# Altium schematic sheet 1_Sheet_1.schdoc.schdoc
size 495 x 241 mm; Name: A_A4; Symbol: A_A4; Device: A_A4; @Project Name: pupnik_2023-12-26_01-16-22; REV: 1.0; Date: 2023-12-25; Sheet: 1/1; Draw By: Penguin Kothe; Company: Your Company; Convert to PCB: yes; Add into BOM: yes
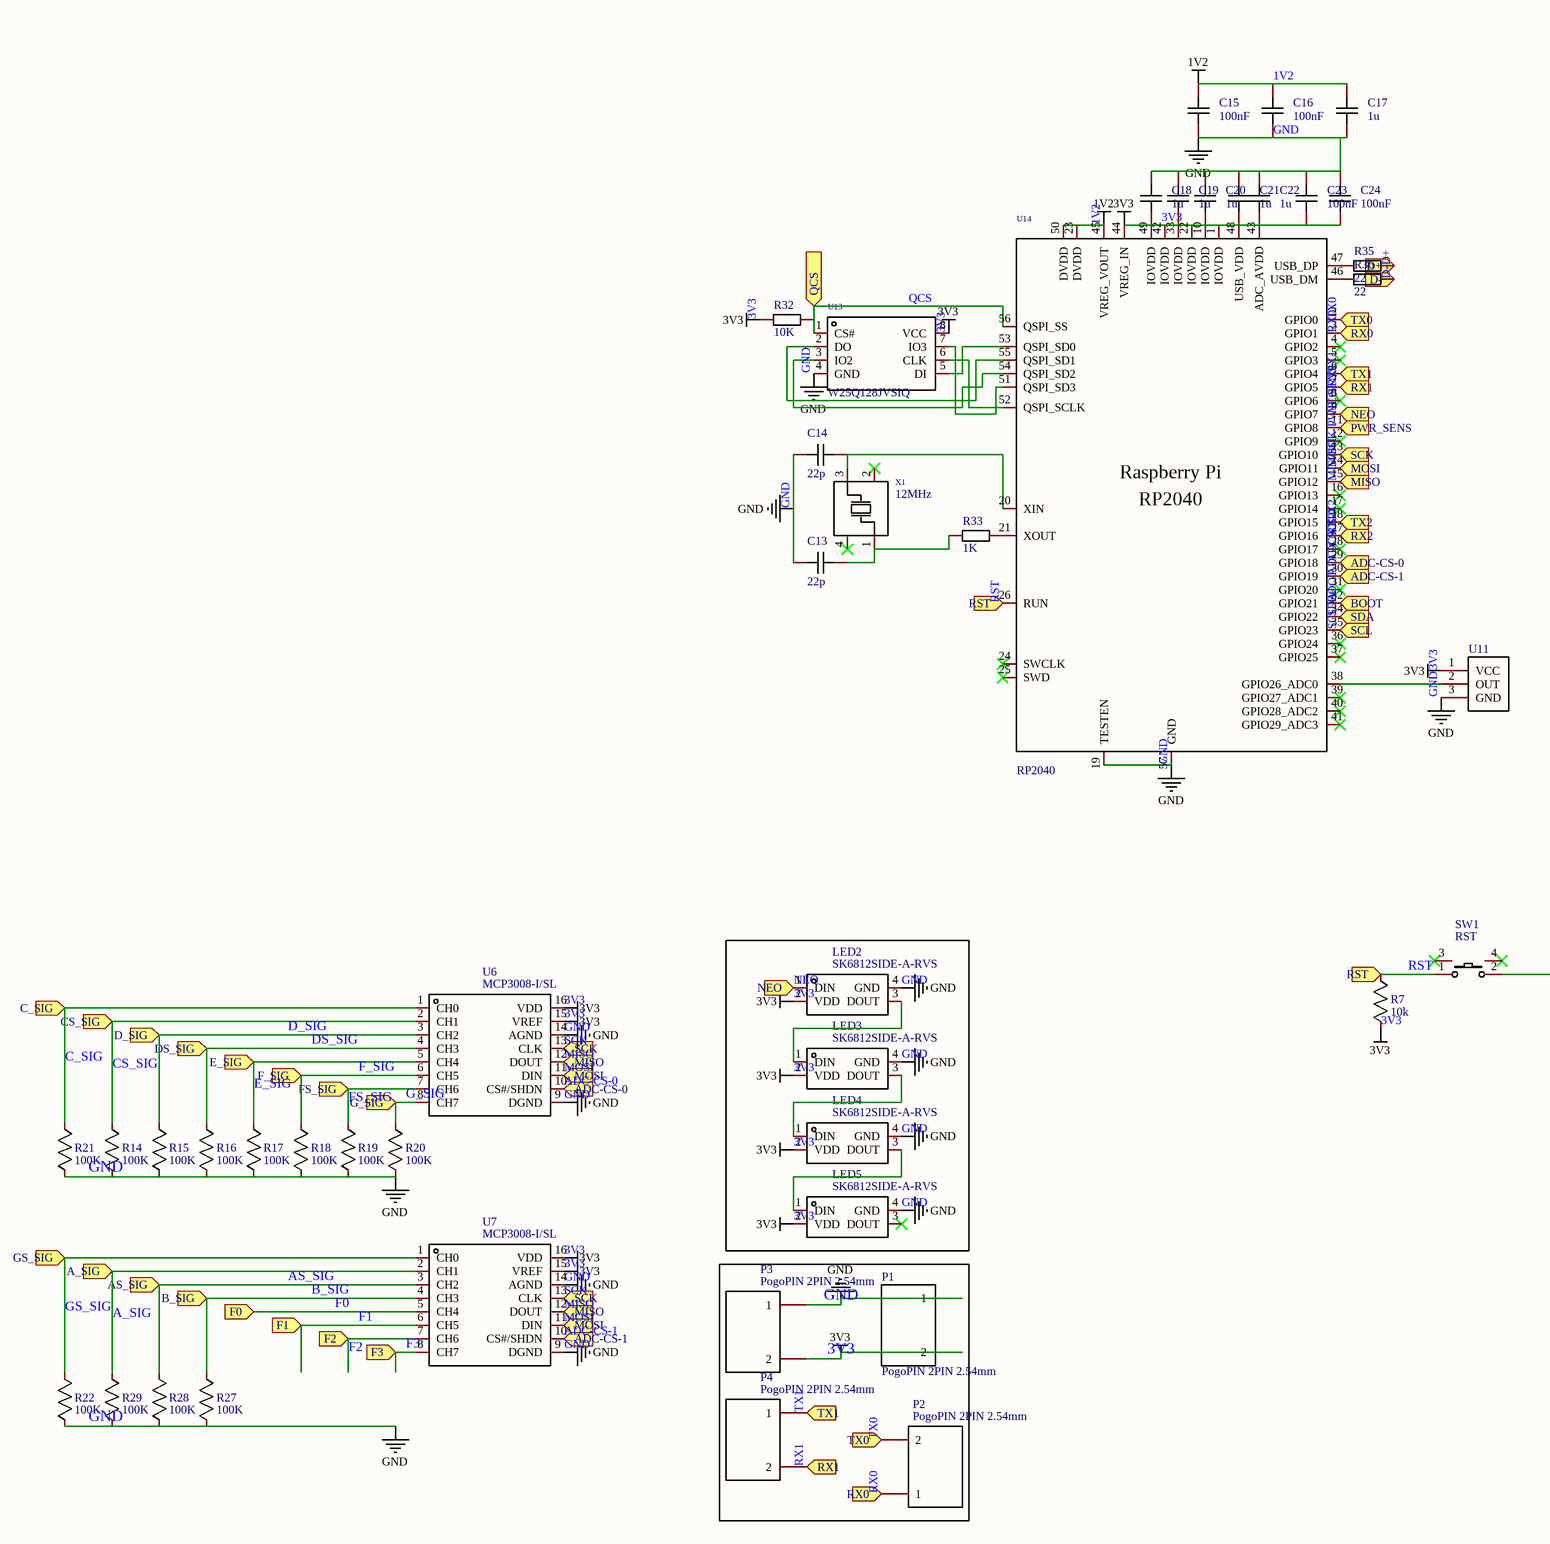
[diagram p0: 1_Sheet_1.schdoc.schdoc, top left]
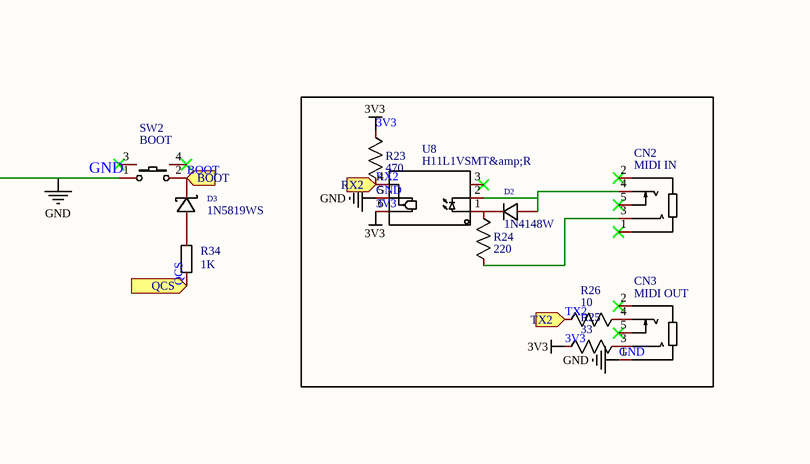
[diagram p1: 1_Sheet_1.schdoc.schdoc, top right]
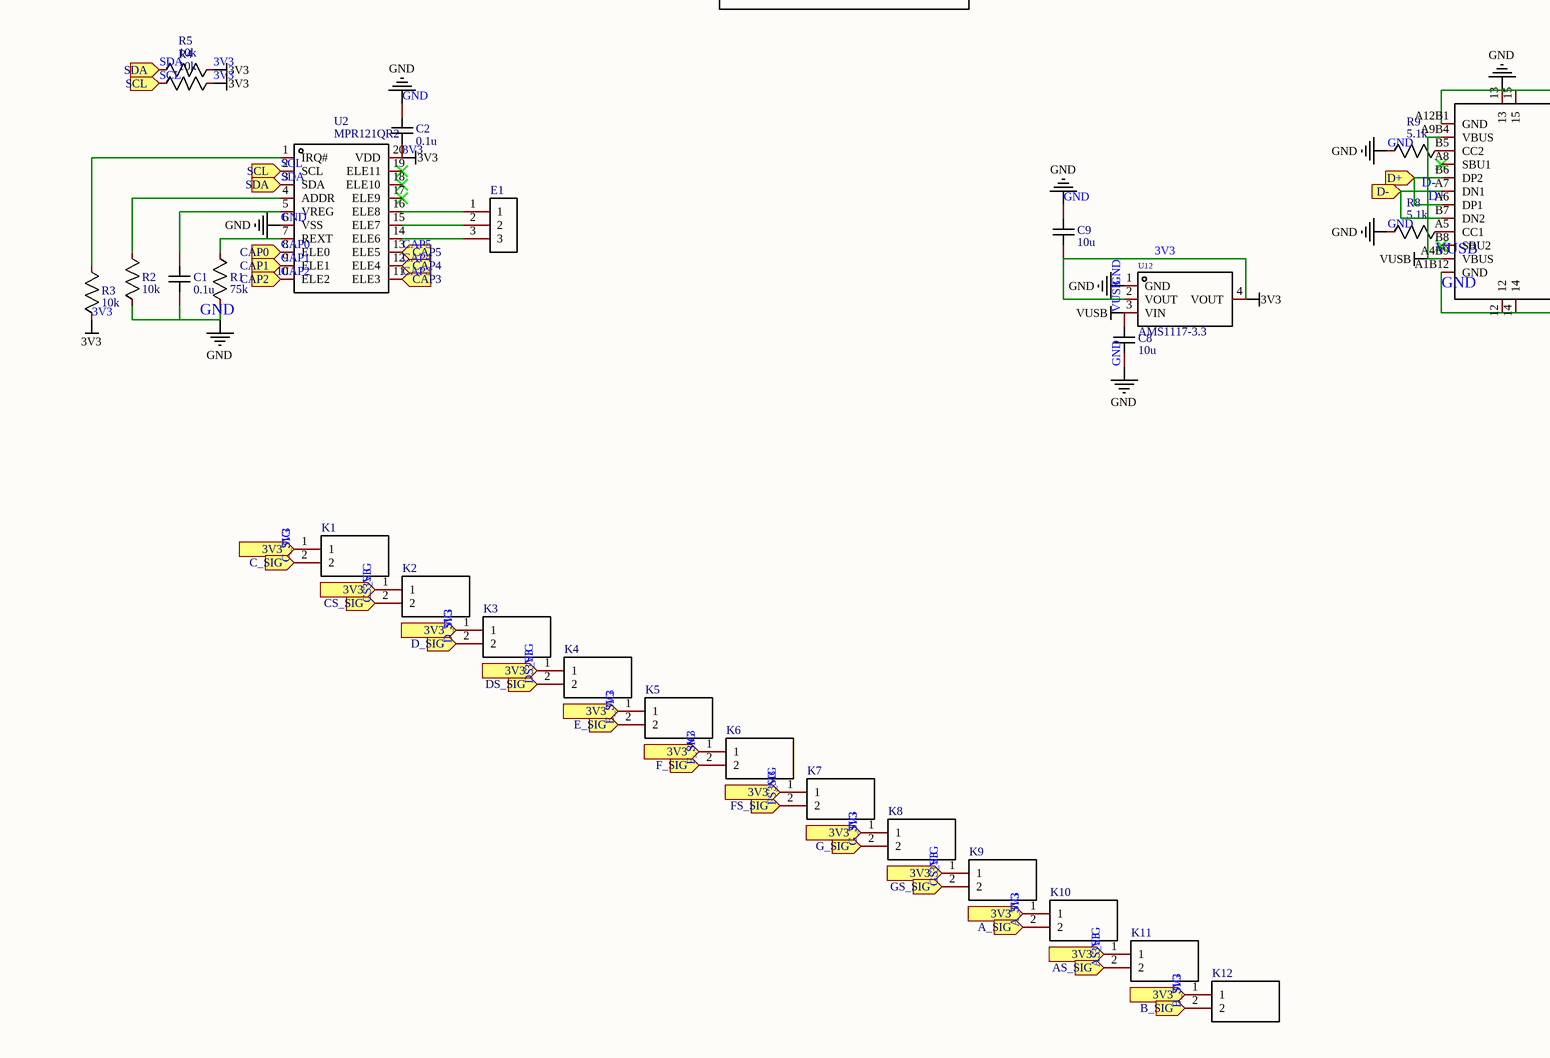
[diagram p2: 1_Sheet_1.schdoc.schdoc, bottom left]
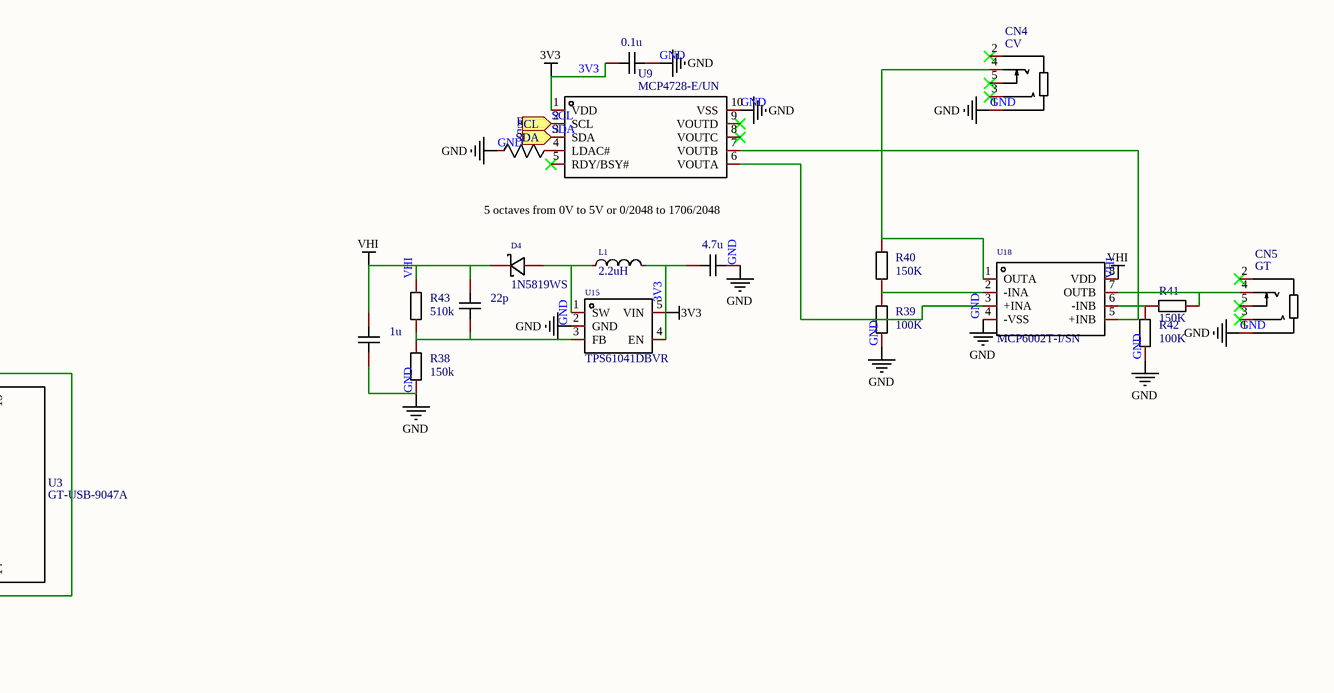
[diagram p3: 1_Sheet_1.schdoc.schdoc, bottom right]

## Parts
C1  0.1u  [C0603]
C2  0.1u  [C0603]
C8  10u  [C0603]
C9  10u  [C0603]
C12  0.1u  [C0603]
C13  22p  [C0603]
C14  22p  [C0603]
C15  100nF  [C0603]
C16  100nF  [C0603]
C17  1u  [C0603]
C18  1u  [C0603]
C19  1u  [C0603]
C20  1u  [C0603]
C21  1u  [C0603]
C22  1u  [C0603]
C23  100nF  [C0603]
C24  100nF  [C0603]
C25  4.7u  [C0603]
C26  22p  [C0603]
C27  1u  [C0603]
CN2  MIDI IN  [AUDIO-SMD_PJ-327A5JJ]
CN3  MIDI OUT  [AUDIO-SMD_PJ-327A5JJ]
CN4  CV  [AUDIO-SMD_PJ-327A5JJ]
CN5  GT  [AUDIO-SMD_PJ-327A5JJ]
D2  1N4148W  [SOD-123F_L2.7-W1.6-LS3.8-RD]
D3  1N5819WS  [SOD-323_L1.8-W1.3-LS2.5-RD]
D4  1N5819WS  [SOD-323_L1.8-W1.3-LS2.5-RD]
E1  enc  [enc]  (value not drawn)
K1  key  [key]  (value not drawn)
K2  key  [key]  (value not drawn)
K3  key  [key]  (value not drawn)
K4  key  [key]  (value not drawn)
K5  key  [key]  (value not drawn)
K6  key  [key]  (value not drawn)
K7  key  [key]  (value not drawn)
K8  key  [key]  (value not drawn)
K9  key  [key]  (value not drawn)
K10  key  [key]  (value not drawn)
K11  key  [key]  (value not drawn)
K12  key  [key]  (value not drawn)
L1  2.2uH  [L0805]
LED2  SK6812SIDE-A-RVS  [LED-SMD_4P-L4.0-W1.6-L]
LED3  SK6812SIDE-A-RVS  [LED-SMD_4P-L4.0-W1.6-L]
LED4  SK6812SIDE-A-RVS  [LED-SMD_4P-L4.0-W1.6-L]
LED5  SK6812SIDE-A-RVS  [LED-SMD_4P-L4.0-W1.6-L]
P1  PogoPIN 2PIN 2.54mm  [POGOPIN 2PIN 2.5MM]
P2  PogoPIN 2PIN 2.54mm  [POGOPIN 2PIN 2.5MM]
P3  PogoPIN 2PIN 2.54mm  [POGOPIN 2PIN 2.5MM]
P4  PogoPIN 2PIN 2.54mm  [POGOPIN 2PIN 2.5MM]
R1  75k  [R0603]
R2  10k  [R0603]
R3  10k  [R0603]
R4  10k  [R0603]
R5  10k  [R0603]
R7  10k  [R0603]
R8  5.1k  [R0603]
R9  5.1k  [R0603]
R14  100K  [R0603]
R15  100K  [R0603]
R16  100K  [R0603]
R17  100K  [R0603]
R18  100K  [R0603]
R19  100K  [R0603]
R20  100K  [R0603]
R21  100K  [R0603]
R22  100K  [R0603]
R23  470  [R0603]
R24  220  [R0603]
R25  33  [R0603]
R26  10  [R0603]
R27  100K  [R0603]
R28  100K  [R0603]
R29  100K  [R0603]
R30  5.1k  [R0603]
R32  10K  [R0603]
R33  1K  [R0603]
R34  1K  [R0603]
R35  22  [R0402]
R36  22  [R0402]
R38  150k  [R0402]
R39  100K  [R0402]
R40  150K  [R0402]
R41  150K  [R0402]
R42  100K  [R0402]
R43  510k  [R0402]
SW1  RST  [SW-SMD_L4.7-W3.5-P3.35-EH]
SW2  BOOT  [SW-SMD_L4.7-W3.5-P3.35-EH]
U2  MPR121QR2  [QFN-20_L3.0-W3.0-P0.40-BL]
U3  GT-USB-9047A  [USB-C-SMD_GT-USB-9047A]
U6  MCP3008-I/SL  [SOIC-16_L9.9-W3.9-P1.27-LS6.0-BL]
U7  MCP3008-I/SL  [SOIC-16_L9.9-W3.9-P1.27-LS6.0-BL]
U8  H11L1VSMT&amp;R  [SMD-6_L8.6-W6.4-P2.54-LS9.4-BL]
U9  MCP4728-E/UN  [MSOP-10_L3.0-W3.0-P0.50-LS5.0-TL]
U11  farts  [farts]  (value not drawn)
U12  AMS1117-3.3  [SOT-223-3_L6.5-W3.4-P2.30-LS7.0-BR]
U13  W25Q128JVSIQ  [SOIC-8_L5.3-W5.3-P1.27-LS8.0-BL]
U14  RP2040  [LQFN-56_L7.0-W7.0-P0.4-EP]
U15  TPS61041DBVR  [SOT-23-5_L3.0-W1.7-P0.95-LS2.8-BR]
U18  MCP6002T-I/SN  [SOIC-8_L4.9-W3.9-P1.27-LS6.0-BL]
X1  12MHz  [OSC-SMD_4P-L3.2-W2.5-BL]

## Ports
3V3 (in), A_SIG (in), ADC-CS-0 (in), ADC-CS-1 (in), AS_SIG (in), B_SIG (in), BOOT (in), C_SIG (in), CAP0 (in), CAP1 (in), CAP2 (in), CAP3 (in), CAP4 (in), CAP5 (in), CS_SIG (in), D+ (in), D- (in), D_SIG (in), DS_SIG (in), E_SIG (in), F0 (in), F1 (in), F2 (in), F3 (in), F_SIG (in), FS_SIG (in), G_SIG (in), GS_SIG (in), MISO (in), MOSI (in), NEO (in), PWR_SENS (in), QCS (in), RST (in), RX0 (in), RX1 (in), RX2 (in), SCK (in), SCL (in), SDA (in), TX0 (in), TX1 (in), TX2 (in)

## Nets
1V2: C15.1 C16.1 C17.1 U14.23(DVDD) U14.45(VREG_VOUT) U14.50(DVDD)
3V3: C2.1 C9.1 C12.2 C18.2 C19.2 C20.2 C21.2 C22.2 C23.2 C24.2 C25.2 K1.1 K2.1 K3.1 K4.1 K5.1 K6.1 K7.1 K8.1 K9.1 K10.1 K11.1 K12.1 L1.2 LED2.2(VDD) LED3.2(VDD) LED4.2(VDD) LED5.2(VDD) P1.2 P3.2 R3.1 R4.1 R5.1 R7.1 R23.2 R25.2 R32.1 U2.20(VDD) U6.15(VREF) U6.16(VDD) U7.15(VREF) U7.16(VDD) U8.6(VCC) U9.1(VDD) U11.1(VCC) U12.2(VOUT) U12.4(VOUT) U13.8(VCC) U14.1(IOVDD) U14.10(IOVDD) U14.22(IOVDD) U14.33(IOVDD) U14.42(IOVDD) U14.43(ADC_AVDD) U14.44(VREG_IN) U14.48(USB_VDD) U14.49(IOVDD) U15.4(EN) U15.5(VIN) ; port 3V3
D+: C8.2 R35.2 U3.A4B9(VBUS) U3.A6(DP1) U3.A9B4(VBUS) U3.B6(DP2) U12.3(VIN) ; port D+  [also labelled VUSB]
GND: C1.1 C2.2 C8.1 C9.2 C12.1 C13.1 C14.2 C15.2 C16.2 C17.2 C18.1 C19.1 C20.1 C21.1 C22.1 C23.1 C24.1 C25.1 C27.2 CN3.1 CN4.1 CN5.1 LED2.4(GND) LED3.4(GND) LED4.4(GND) LED5.4(GND) P1.1 P3.1 R1.1 R2.1 R8.1 R9.1 R14.1 R15.1 R16.1 R17.1 R18.1 R19.1 R20.1 R21.1 R22.1 R27.1 R28.1 R29.1 R30.1 R38.1 R39.1 R42.1 SW1.2 SW2.1 U2.6(VSS) U3.12 U3.13 U3.14 U3.15 U3.A1B12(GND) U3.A12B1(GND) U6.9(DGND) U6.14(AGND) U7.9(DGND) U7.14(AGND) U8.5(GND) U9.10(VSS) U11.3(GND) U12.1(GND) U13.4(GND) U14.19(TESTEN) U14.57(GND) U15.2(GND) U18.4(-VSS)
VHI: C26.1 C27.1 D4.1(K) R43.2 U18.8(VDD)
A_SIG: K10.2 R29.2 U7.2(CH1) ; port A_SIG
ADC-CS-0: U6.10(CS#/SHDN) U14.29(GPIO18) ; port ADC-CS-0
ADC-CS-1: U7.10(CS#/SHDN) U14.30(GPIO19) ; port ADC-CS-1
AS_SIG: K11.2 R28.2 U7.3(CH2) ; port AS_SIG
B_SIG: K12.2 R27.2 U7.4(CH3) ; port B_SIG
BOOT: D3.1(K) SW2.2 U14.32(GPIO21) ; port BOOT
C_SIG: K1.2 R21.2 U6.1(CH0) ; port C_SIG
CAP0: U2.8(ELE0) ; port CAP0
CAP1: U2.9(ELE1) ; port CAP1
CAP2: U2.10(ELE2) ; port CAP2
CAP3: U2.11(ELE3) ; port CAP3
CAP4: U2.12(ELE4) ; port CAP4
CAP5: U2.13(ELE5) ; port CAP5
CS_SIG: K2.2 R14.2 U6.2(CH1) ; port CS_SIG
D-: R36.2 U3.A7(DN1) U3.B7(DN2) ; port D-
D_SIG: K3.2 R15.2 U6.3(CH2) ; port D_SIG
DS_SIG: K4.2 R16.2 U6.4(CH3) ; port DS_SIG
E_SIG: K5.2 R17.2 U6.5(CH4) ; port E_SIG
F0: U7.5(CH4) ; port F0
F1: U7.6(CH5) ; port F1
F2: U7.7(CH6) ; port F2
F3: U7.8(CH7) ; port F3
F_SIG: K6.2 R18.2 U6.6(CH5) ; port F_SIG
FS_SIG: K7.2 R19.2 U6.7(CH6) ; port FS_SIG
G_SIG: K8.2 R20.2 U6.8(CH7) ; port G_SIG
GS_SIG: K9.2 R22.2 U7.1(CH0) ; port GS_SIG
MISO: U6.12(DOUT) U7.12(DOUT) U14.15(GPIO12) ; port MISO
MOSI: U6.11(DIN) U7.11(DIN) U14.14(GPIO11) ; port MOSI
NEO: LED2.1(DIN) U14.9(GPIO7) ; port NEO
PWR_SENS: U14.11(GPIO8) ; port PWR_SENS
QCS: R32.2 R34.1 U13.1(CS#) U14.56(QSPI_SS) ; port QCS
RST: R7.2 SW1.1 U14.26(RUN) ; port RST
RX0: P2.1 U14.3(GPIO1) ; port RX0
RX1: P4.2 U14.7(GPIO5) ; port RX1
RX2: R23.1 U8.4(VO) U14.27(GPIO16) ; port RX2
SCK: U6.13(CLK) U7.13(CLK) U14.13(GPIO10) ; port SCK
SCL: R4.2 U2.2(SCL) U9.2(SCL) U14.35(GPIO23) ; port SCL
SDA: R5.2 U2.3(SDA) U9.3(SDA) U14.34(GPIO22) ; port SDA
TX0: P2.2 U14.2(GPIO0) ; port TX0
TX1: P4.1 U14.6(GPIO4) ; port TX1
TX2: R26.2 U14.18(GPIO15) ; port TX2
NetC1_2: C1.2 U2.5(VREG)
NetC13_2: C13.2 R33.1 X1.1(OSC1)
NetC14_1: C14.1 U14.20(XIN) X1.3(OSC2)
NetC26_2: C26.2 R38.2 R43.1 U15.3(FB)
NetCN2_3: CN2.3 R24.1
NetCN2_4: CN2.4 D2.2(A) U8.2(C)
NetCN3_3: CN3.3 R25.1
NetCN3_4: CN3.4 R26.1
NetCN4_4: CN4.4 R40.2 U18.1(OUTA)
NetCN5_4: CN5.4 R41.1 U18.7(OUTB)
NetD2_1: D2.1(K) R24.2 U8.1(A)
NetD3_2: D3.2(A) R34.2
NetD4_2: D4.2(A) L1.1 U15.1(SW)
NetE1_1: E1.1 U2.16(ELE8)
NetE1_2: E1.2 U2.15(ELE7)
NetE1_3: E1.3 U2.14(ELE6)
NetLED2_3: LED2.3(DOUT) LED3.1(DIN)
NetLED3_3: LED3.3(DOUT) LED4.1(DIN)
NetLED4_3: LED4.3(DOUT) LED5.1(DIN)
NetR1_2: R1.2 U2.7(REXT)
NetR2_2: R2.2 U2.4(ADDR)
NetR3_2: R3.2 U2.1(IRQ#)
NetR8_2: R8.2 U3.A5(CC1)
NetR9_2: R9.2 U3.B5(CC2)
NetR30_2: R30.2 U9.4(LDAC#)
NetR33_2: R33.2 U14.21(XOUT)
NetR35_1: R35.1 U14.47(USB_DP)
NetR36_1: R36.1 U14.46(USB_DM)
NetR39_2: R39.2 R40.1 U18.2(-INA)
NetR41_2: R41.2 R42.2 U18.6(-INB)
NetU9_6: U9.6(VOUTA) U18.3(+INA)
NetU9_7: U9.7(VOUTB) U18.5(+INB)
NetU11_2: U11.2(OUT) U14.38(GPIO26_ADC0)
NetU13_2: U13.2(DO) U14.55(QSPI_SD1)
NetU13_3: U13.3(IO2) U14.54(QSPI_SD2)
NetU13_5: U13.5(DI) U14.53(QSPI_SD0)
NetU13_6: U13.6(CLK) U14.52(QSPI_SCLK)
NetU13_7: U13.7(IO3) U14.51(QSPI_SD3)

Not connected (* = marked no-connect by the designer): CN2 1* 2* 5*; CN3 2* 5*; CN4 2* 3* 5*; CN5 2* 3* 5*; LED5 3(DOUT)*; SW1 3* 4*; SW2 3* 4*; U2 17(ELE9)* 18(ELE10)* 19(ELE11)*; U3 A8(SBU1)* B8(SBU2)*; U8 3(NC)*; U9 5(RDY/BSY#)* 8(VOUTC)* 9(VOUTD)*; U14 4(GPIO2)* 5(GPIO3)* 8(GPIO6)* 12(GPIO9)* 16(GPIO13)* 17(GPIO14)* 24(SWCLK)* 25(SWD)* 28(GPIO17)* 31(GPIO20)* 36(GPIO24)* 37(GPIO25)* 39(GPIO27_ADC1)* 40(GPIO28_ADC2)* 41(GPIO29_ADC3)*; X1 2(GND)* 4(GND)*

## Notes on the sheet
- 5 octaves from 0V to 5V or 0/2048 to 1706/2048

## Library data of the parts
C1 C2 C12 C25-C27 = 0.1u: Convert to PCB: yes
C8 C9 = 10u: Convert to PCB: yes
C13-C24 = CAP_0603: Symbol: CAP; Convert to PCB: yes
CN2 = MIDI IN: Manufacturer: SHOU HAN(首韩); Manufacturer Part: PJ-327A 5JJ; Convert to PCB: yes
CN3 = MIDI OUT: Manufacturer: SHOU HAN(首韩); Manufacturer Part: PJ-327A 5JJ; Convert to PCB: yes
CN4 = CV: Manufacturer: SHOU HAN(首韩); Manufacturer Part: PJ-327A 5JJ; Convert to PCB: yes
CN5 = GT: Manufacturer: SHOU HAN(首韩); Manufacturer Part: PJ-327A 5JJ; Convert to PCB: yes
D2 = 1N4148W_C81598: Diode Configuration: Forward Voltage (Vf@If):1V@50mA Reverse Voltage (Vr): Average Rectified Current (Io): Power Dissipation: Reverse Leakage Current:1uA@75V Reverse Recovery Time (trr): Operating Temperature:- Operating Temperature:-; Manufacturer: ST(先科); Add into BOM: yes
D3 D4 = 1N5819WS_C191023: Forward Voltage (Vf@If):600mV@1A Reverse Voltage (Vr):40V Average Rectified Current (Io):1A; Manufacturer: Hottech(合科泰); Add into BOM: yes; Reverse Voltage (Vr): 40V; Average Rectified Current (Io): 1A
E1 = enc: Add into BOM: yes
K1-K12 = key: Add into BOM: yes
L1 = CMI201209U2R2KT: Inductance: Tolerance:±10% Tolerance:±10% Rated Current: DC Resistance (DCR): Saturation Current (Isat):- Q @ Freq:35@10MHz Frequency - Self Resonant: Ratings:; Manufacturer: FH(风华); Add into BOM: yes; Tolerance: ±10%
LED2-LED5 = SK6812SIDE-A-RVS: Manufacturer: 欧思科光电; Convert to PCB: yes
P1-P4 = PogoPIN 2PIN 2.54mm: Convert to PCB: yes
R1 = 75k: Convert to PCB: yes
R2-R5 = 10k: Convert to PCB: yes
R7-R9 R30 = 5.1k: Convert to PCB: yes
R14-R22 R27-R29 = 100K: Convert to PCB: yes
R23 = 470: Convert to PCB: yes
R24 = 220: Convert to PCB: yes
R25 = 33: Convert to PCB: yes
R26 = 10: Convert to PCB: yes
R32-R34 = Res_0603: Symbol: Res; Convert to PCB: yes
R35 R36 R38-R43 = Res_0402: Symbol: Res; Convert to PCB: yes
SW1 = RST: Manufacturer: SHOU HAN(首韩); Manufacturer Part: TS24CA 250gf 013; Convert to PCB: yes
SW2 = BOOT: Manufacturer: SHOU HAN(首韩); Manufacturer Part: TS24CA 250gf 013; Convert to PCB: yes
U2 = MPR121QR2: Manufacturer: NXP(恩智浦); Convert to PCB: yes
U3 = GT-USB-9047A: Manufacturer: G-Switch(品赞); Convert to PCB: yes
U6 U7 = MCP3008-I/SL: Manufacturer: MICROCHIP(美国微芯); Convert to PCB: yes
U8 = H11L1VSMT&amp;R: Manufacturer: ISOCOM(英国安数光); Symbol: H11L1VSMT&amp;amp;R; Convert to PCB: yes
U9 = MCP4728-E/UN: Manufacturer: MICROCHIP(美国微芯); Convert to PCB: yes
U11 = farts: Add into BOM: yes
U12 = AMS1117-3.3_C6186: Output Type: Maximum Input Voltage:- Output Voltage:3.3V Output Voltage:3.3V Output Current:1A Power Supply Rejection Ratio (PSRR):72dB@(120Hz) Dropout Voltage:1.3V@(800mA) Quiescent Current (Ground Current):- Noise:- Feature:- Operating Temperature:- Ope; Manufacturer: AMS; Add into BOM: yes; Output Voltage: 3.3V; Output Current: 1A; Output Polarity: Positive; Number of Outputs: 1
U13 = W25Q128JVSIQ: Interface Type:- Memory Size:128Mbit Clock Frequency (fc):- Supply Voltage:- Supply Voltage:- Supply Current (Read):- Supply Current (Program):- Supply Current (Erase):- Standby supply current:- Page Programming Time (Tpp):- Block Erase Time (tBE):- Data; Manufacturer: WINBOND(华邦); Symbol: W25Q128JVSIQTR; Add into BOM: yes
U14 = RP2040_C2040: CPU Core:ARM-MSeries CPU Maximum Speed:133MHz Program Storage Size:- Program Memory Type:- GPIO Ports Number:30 Operating Voltage Range:- Operating Voltage Range:- RAM Size:264KB EEPROM:- Operating Temperature Range:- Operating Temperature Range:- ADC (Bi; Manufacturer: Raspberry Pi(树莓派); Add into BOM: yes; CPU Maximum Speed: 133MHz; GPIO Ports Number: 30; RAM Size: 264KB; ADC (Bit): 12bit; UART/USART: 2; Universal Serial Bus: 有; Peripheral/Function: DMA；PWM
U15 = TPS61041DBVR: Function:boost converterType Synchronous Rectification:NO Number of Outputs:1 Topology:Boost Input Voltage:1.8V~6V Input Voltage:1.8V~6V Output Voltage:28V Output Voltage:28V Output Current (Max):215mA Switching Frequency:1MHz; Manufacturer: TI(德州仪器); Add into BOM: yes; Synchronous Rectification: NO; Number of Outputs: 1; Topology: Boost; Output Voltage: 28V; Output Current (Max): 215mA; Switching Frequency: 1MHz
U18 = MCP6002T-I/SN: Number of Circuits: -3db Bandwidth:- Current - Input Bias(Ib):1pA Gain Bandwidth Product(GBP):1MHz Slew Rate(SR):0.6V/us Output Current:23mA Supply Voltage:1.8V~6V Supply Voltage:1.8V~6V Supply Current:100uA Operating Temperature:-40℃~+85℃ Operating Tempe; Manufacturer: MICROCHIP(美国微芯); Add into BOM: yes; Current - Input Bias(Ib): 1pA; Gain Bandwidth Product(GBP): 1MHz; Output Current: 23mA; Supply Current: 100uA
X1 = X322512MSB4SI: Crystal Type:SMD Crystal Resonator Frequency: Load Capacitance: Frequency Tolerance:±10ppm Frequency Tolerance:±10ppm Frequency Stability:±30ppm Frequency Stability:±30ppm Operating Temperature: Operating Temperature:; Manufacturer: YXC(扬兴晶振); Add into BOM: yes; Frequency Tolerance: ±10ppm; Frequency Stability: ±30ppm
